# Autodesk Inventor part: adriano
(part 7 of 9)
sketch "スケッチ204"
  geometry: L1 (10, 18.464)-(6, 18.464) reference; L2 (10, 24.464)-(10, 18.464) reference; L3 (6.75, 24.064)-(7.75, 24.064); L4 (7.75, 24.064)-(7.75, 22.864); L5 (7.75, 22.864)-(6.75, 22.864); L6 (6.75, 22.864)-(6.75, 24.064); L7 (8.25, 24.064)-(9.25, 24.064); L8 (9.25, 24.064)-(9.25, 22.864); L9 (9.25, 22.864)-(8.25, 22.864); L10 (8.25, 22.864)-(8.25, 24.064); L11 (6.75, 22.364)-(7.75, 22.364); L12 (7.75, 22.364)-(7.75, 21.164); L13 (7.75, 21.164)-(6.75, 21.164); L14 (6.75, 21.164)-(6.75, 22.364); L15 (8.25, 22.364)-(9.25, 22.364); L16 (9.25, 22.364)-(9.25, 21.164); L17 (9.25, 21.164)-(8.25, 21.164); L18 (8.25, 21.164)-(8.25, 22.364); L19 (6.75, 20.664)-(7.75, 20.664); L20 (7.75, 20.664)-(7.75, 19.464); L21 (7.75, 19.464)-(6.75, 19.464); L22 (6.75, 19.464)-(6.75, 20.664); L23 (8.25, 20.664)-(9.25, 20.664); L24 (9.25, 20.664)-(9.25, 19.464); L25 (9.25, 19.464)-(8.25, 19.464); L26 (8.25, 19.464)-(8.25, 20.664); L27 (22.25, 22.364)-(23.25, 22.364); L28 (23.25, 22.364)-(23.25, 21.164); L29 (23.25, 21.164)-(22.25, 21.164); L30 (22.25, 21.164)-(22.25, 22.364); L31 (21.75, 22.364)-(21.75, 21.164); L32 (21.75, 21.164)-(20.75, 21.164); L33 (20.75, 21.164)-(20.75, 22.364); L34 (23.25, 22.864)-(22.25, 22.864); L35 (22.25, 22.864)-(22.25, 24.064); L36 (23.25, 24.064)-(23.25, 22.864); L37 (22.25, 24.064)-(23.25, 24.064); L38 (20.75, 20.664)-(21.75, 20.664); L39 (22.25, 20.664)-(23.25, 20.664); L40 (21.75, 20.664)-(21.75, 19.464); L41 (20.75, 19.464)-(20.75, 20.664); L42 (22.25, 19.464)-(22.25, 20.664); L43 (23.25, 20.664)-(23.25, 19.464); L44 (23.25, 19.464)-(22.25, 19.464); L45 (21.75, 19.464)-(20.75, 19.464); L46 (20.75, 22.364)-(21.75, 22.364); L47 (21.75, 22.864)-(20.75, 22.864); L48 (21.75, 24.064)-(21.75, 22.864); L49 (20.75, 22.864)-(20.75, 24.064); L50 (20.75, 24.064)-(21.75, 24.064); L51 (-5.75, 19.464)-(-5.75, 20.664); L52 (-4.75, 20.664)-(-4.75, 19.464); L53 (-4.75, 19.464)-(-5.75, 19.464); L54 (-7.25, 19.464)-(-7.25, 20.664); L55 (-6.25, 19.464)-(-7.25, 19.464); L56 (-6.25, 20.664)-(-6.25, 19.464); L57 (-7.25, 24.105)-(-6.25, 24.105); L58 (-6.25, 24.105)-(-6.25, 22.864); L59 (-6.25, 22.864)-(-7.25, 22.864); L60 (-7.25, 22.864)-(-7.25, 24.105); L61 (-5.75, 24.064)-(-4.75, 24.064); L62 (-4.75, 24.064)-(-4.75, 22.864); L63 (-7.25, 22.364)-(-6.25, 22.364); L64 (-5.75, 22.864)-(-5.75, 24.064)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; A1 r 1 centre (7.75, 24.564) between (7.75, 25.564) and (6.75, 24.564); A2 r 1 centre (8.25, 24.564) between (9.25, 24.564) and (8.25, 25.564); 7 further points
  constraints: 152 end point, 37 parallel, 21 perpendicular, 18 horizontal, 4 point on circle, 2 centre point
  dimensions: "d3442" = 1 distance of L3.start L3.end; "d3444" = 1 distance of L7.start L7.end; "d3445" = 0.5 distance between parallel lines of L10 L4; "d3446" = 0 distance between parallel lines of L18 L10; "d3447" = 0 distance between parallel lines of L18 L26; "d3448" = 0 distance between parallel lines of L16 L8; "d3449" = 0 distance between parallel lines of L24 L16; "d3450" = 1.2 distance of L7.end L8.end; "d3451" = 0.5 distance between parallel lines of L15 L9; "d3452" = 1.2 distance of L15.end L16.end; "d3453" = 0.5 distance between parallel lines of L23 L17; "d3454" = 1.2 distance of L23.end L24.end; "d3455" = 0 distance between parallel lines of L9 L5; "d3456" = 0 distance between parallel lines of L15 L11; "d3458" = 0 distance between parallel lines of L17 L13; "d3459" = 0 distance between parallel lines of L23 L19; "d3460" = 0 distance between parallel lines of L25 L21; "d3461" = 1 distance between parallel lines of L1 L25; "d3462" = 0.75 distance between parallel lines of L2 L24; "d3463" = 0 distance between parallel lines of L20 L12; "d3464" = 0 distance between parallel lines of L12 L4; "d3465" = 0 distance between parallel lines of L22 L14; "d3466" = 0 distance between parallel lines of L14 L6; "d3467" = 1 distance of L49.end L48.start; "d3468" = 1 distance of L35.end L36.start; "d3469" = 0.5 distance between parallel lines of L35 L48; "d3470" = 0 distance between parallel lines of L30 L35; "d3471" = 0 distance between parallel lines of L30 L42; "d3472" = 0 distance between parallel lines of L28 L36; "d3473" = 0 distance between parallel lines of L43 L28; "d3474" = 1.2 distance of L36.start L34.start; "d3475" = 0.5 distance between parallel lines of L27 L34; "d3476" = 1.2 distance of L27.end L28.end; "d3477" = 0.5 distance between parallel lines of L39 L29; "d3478" = 1.2 distance of L39.end L43.end; "d3479" = 0 distance between parallel lines of L34 L47; "d3480" = 0 distance between parallel lines of L27 L46; "d3481" = 0 distance between parallel lines of L29 L32; "d3482" = 0 distance between parallel lines of L39 L38; "d3483" = 0 distance between parallel lines of L44 L45; "d3484" = 0 distance between parallel lines of L40 L31; "d3485" = 0 distance between parallel lines of L31 L48; "d3486" = 0 distance between parallel lines of L41 L33; "d3487" = 0 distance between parallel lines of L33 L49; "d3488" = 1 distance of L57.start L57.end; "d3489" = 1 distance of L61.start L61.end; "d3490" = 0.5 distance between parallel lines of L64 L58; "d3491" = 0 distance between parallel lines of L71 L64; "d3492" = 0 distance between parallel lines of L71 L51; "d3493" = 0 distance between parallel lines of L69 L62; "d3494" = 0 distance between parallel lines of L52 L69; "d3495" = 1.2 distance of L61.end L62.end; "d3496" = 0.5 distance between parallel lines of L68 L70; "d3497" = 1.2 distance of L68.end L67.start; "d3498" = 0.5 distance between parallel lines of L65 L67; "d3499" = 1.2 distance of L52.start L52.end; "d3500" = 0 distance between parallel lines of L70 L59; "d3501" = 0 distance between parallel lines of L68 L63; "d3502" = 0 distance between parallel lines of L67 L66; "d3503" = 0 distance between parallel lines of L65 L74; "d3504" = 0 distance between parallel lines of L53 L55; "d3505" = 0 distance between parallel lines of L56 L73; "d3506" = 0 distance between parallel lines of L73 L58; "d3507" = 0 distance between parallel lines of L54 L72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
extrude "押し出し193" cut sketch "スケッチ204" distance "d3515" = 16; taper "d3516" = 0 deg
sketch "スケッチ205"
  geometry: L1 (12.25, 5.3)-(12.25, 6.5) reference; L2 (12.25, 6.5)-(13.25, 6.5) reference; L3 (13.25, 6.5)-(13.25, 5.3) reference; L4 (13.25, 5.3)-(12.25, 5.3) reference; L5 (12.25, 7)-(12.25, 8.2) reference; L6 (12.25, 8.2)-(13.25, 8.2) reference; L7 (13.25, 8.2)-(13.25, 7) reference; L8 (13.25, 7)-(12.25, 7) reference; L9 (10.75, 4.8)-(11.75, 4.8) reference; L10 (11.75, 4.8)-(11.75, 3.6) reference; L11 (11.75, 3.6)-(10.75, 3.6) reference; L12 (10.75, 3.6)-(10.75, 4.8) reference; L13 (13.25, 4.8)-(13.25, 3.6) reference; L14 (13.25, 3.6)-(12.25, 3.6) reference; L15 (12.25, 3.6)-(12.25, 4.8) reference; L16 (12.25, 4.8)-(13.25, 4.8) reference; L17 (10.75, 5.3)-(10.75, 6.5) reference; L18 (10.75, 6.5)-(11.75, 6.5) reference; L19 (11.75, 6.5)-(11.75, 5.3) reference; L20 (11.75, 5.3)-(10.75, 5.3) reference; L21 (10.75, 7)-(10.75, 8.241) reference; L22 (10.75, 8.241)-(11.75, 8.241) reference; L23 (11.75, 8.241)-(11.75, 7) reference; L24 (11.75, 7)-(10.75, 7) reference; L25 (9.5, 2.6)-(9.5, 8.6) reference; L26 (14.5, 2.6)-(9.5, 2.6) reference; L27 (10, 9.1)-(14, 9.1); L28 (14, 9.1)-(14, 3.1); L29 (14, 3.1)-(10, 3.1); L30 (10, 3.1)-(10, 9.1); L31 (38, 9.1)-(42, 9.1); L32 (42, 9.1)-(42, 3.1); L33 (42, 3.1)-(38, 3.1); L34 (38, 3.1)-(38, 9.1); L35 (37.5, 2.6)-(37.5, 8.6) reference; 1 further point
  constraints: 16 end point, 4 parallel, 2 horizontal, 2 perpendicular
  dimensions: "d3517" = 4 distance of L28.end L29.end; "d3519" = 4 distance of L32.end L33.end; "d3520" = 0.5 distance between parallel lines of L26 L29; "d3521" = 0 distance between parallel lines of L33 L29; "d3522" = 0.5 distance between parallel lines of L30 L25; "d3523" = 0.5 distance between parallel lines of L35 L34; "d3524" = 6 distance of L31.end L32.end; "d3525" = 0 distance between parallel lines of L31 L27
extrude "押し出し194" cut sketch "スケッチ205" distance "d3526" = 0.5; taper "d3527" = 0 deg
sketch "スケッチ206"
  geometry: L1 (0, 0)-(26, 0) reference; L2 (0, -1.6)-(0, 0) reference; L3 (10.33, 7)-(10.33, 1); L4 (10.33, 1)-(15.33, 1); L5 (15.33, 1)-(15.33, 7); A1 r 2.5 centre (12.83, 7) between (15.33, 7) and (10.33, 7); 1 further point
  constraints: 6 end point, 2 parallel, 2 point on circle, 1 centre point, 1 perpendicular
  dimensions: "d3528" = 1 distance between parallel lines of L1 L4; "d3529" = 5 distance of L3.end L4.end; "d3530" = 6 distance of L4.end L5.end; "d3531" = 0 vertical distance of L5.end A1.centre; "d3532" = 0 vertical distance of A1.centre L3.start
extrude "押し出し195" join sketch "スケッチ206" distance "d3533" = 8; taper "d3534" = 0 deg
sketch "スケッチ207"
  geometry: L1 (10.33, 7)-(10.33, 1) reference; L2 (10.33, 1)-(15.33, 1) reference; L3 (15.33, 1)-(15.33, 7) reference; L4 (10.33, 7)-(10.33, 1); L5 (10.33, 1)-(15.33, 1); L6 (15.33, 1)-(15.33, 7); A1 r 2.5 centre (12.83, 7) between (15.33, 7) and (10.33, 7) reference; A2 r 2.5 centre (12.83, 7) between (15.33, 7) and (10.33, 7); 1 further point
  constraints: 6 end point, 4 tangent, 3 equal length, 2 point on circle, 1 centre point, 1 coincident
extrude "押し出し196" cut sketch "スケッチ207" distance "d3535" = 0.5; taper "d3536" = 0 deg
sketch "スケッチ208"
  geometry: L1 (10.33, 1)-(10.33, 7) reference; L2 (9.83, 7)-(10.33, 7); L3 (15.33, 7)-(15.83, 7); A1 r 2.5 centre (12.83, 7) between (15.33, 7) and (10.33, 7) reference; A2 r 3 centre (12.83, 7) between (15.83, 7) and (9.83, 7); A3 r 2.5 centre (12.83, 7) between (15.33, 7) and (10.33, 7); 1 further point
  constraints: 4 end point, 4 point on circle, 2 centre point, 2 coincident, 1 collinear, 1 perpendicular
  dimensions: "d3537" = 0.5 distance of L2.start L1.end
extrude "押し出し197" join sketch "スケッチ208" distance "d3538" = 8; taper "d3539" = 0 deg
sketch "スケッチ209"
  geometry: L1 (10.33, 1)-(10.33, 7) reference; L2 (9.83, 7)-(10.33, 7) reference; L3 (10.33, 7)-(10.33, 1); L4 (10.33, 1)-(15.33, 1); L5 (15.33, 1)-(15.33, 7); A1 r 3 centre (12.83, 7) between (15.83, 7) and (9.83, 7) reference; A2 r 2.5 centre (12.83, 7) between (15.33, 7) and (10.33, 7); 1 further point
  constraints: 6 end point, 3 perpendicular, 2 point on circle, 2 tangent, 1 centre point, 1 coincident
extrude "押し出し198" cut sketch "スケッチ209" distance "d3540" = 0.5; taper "d3541" = 0 deg
sketch "スケッチ210"
  geometry: L1 (10.33, 1)-(10.33, 7) reference; L2 (15.33, 1)-(10.33, 1) reference; L3 (11.58, 6.6)-(12.58, 6.6); L4 (12.58, 6.6)-(12.58, 5.4); L5 (12.58, 5.4)-(11.58, 5.4); L6 (11.58, 5.4)-(11.58, 6.6); L7 (13.08, 6.6)-(14.08, 6.6); L8 (14.08, 6.6)-(14.08, 5.4); L9 (14.08, 5.4)-(13.08, 5.4); L10 (13.08, 5.4)-(13.08, 6.6); L11 (11.58, 4.9)-(12.58, 4.9); L12 (12.58, 4.9)-(12.58, 3.7); L13 (12.58, 3.7)-(11.58, 3.7); L14 (11.58, 3.7)-(11.58, 4.9); L15 (13.08, 4.9)-(14.08, 4.9); L16 (14.08, 4.9)-(14.08, 3.7); L17 (14.08, 3.7)-(13.08, 3.7); L18 (13.08, 3.7)-(13.08, 4.9); L19 (11.58, 3.2)-(12.58, 3.2); L20 (12.58, 3.2)-(12.58, 2); L21 (12.58, 2)-(11.58, 2); L22 (11.58, 2)-(11.58, 3.2); L23 (13.08, 3.2)-(14.08, 3.2); L24 (14.08, 3.2)-(14.08, 2); L25 (14.08, 2)-(13.08, 2); L26 (13.08, 2)-(13.08, 3.2); 1 further point
  constraints: 48 end point, 12 parallel, 6 horizontal, 6 perpendicular
  dimensions: "d3542" = 1 distance of L3.start L3.end; "d3544" = 1 distance of L7.start L7.end; "d3545" = 0.5 distance between parallel lines of L4 L10; "d3546" = 1.2 distance of L7.end L8.end; "d3547" = 0.5 distance between parallel lines of L9 L15; "d3548" = 0.5 distance between parallel lines of L23 L17; "d3549" = 1.2 distance of L15.end L16.end; "d3550" = 1.2 distance of L23.end L24.end; "d3551" = 0 distance between parallel lines of L16 L8; "d3552" = 0 distance between parallel lines of L18 L10; "d3553" = 0 distance between parallel lines of L26 L18; "d3554" = 0 distance between parallel lines of L25 L21; "d3555" = 0 distance between parallel lines of L9 L5; "d3556" = 0 distance between parallel lines of L15 L11; "d3557" = 0 distance between parallel lines of L17 L13; "d3558" = 0 distance between parallel lines of L23 L19; "d3559" = 1 distance between parallel lines of L2 L21; "d3560" = 1.25 distance between parallel lines of L22 L1; "d3561" = 0 distance between parallel lines of L22 L14; "d3562" = 0 distance between parallel lines of L14 L6; "d3563" = 0 distance between parallel lines of L12 L4; "d3564" = 0 distance between parallel lines of L20 L12
extrude "押し出し199" cut sketch "スケッチ210" distance "d3565" = 16; taper "d3566" = 0 deg
sketch "スケッチ211"
  geometry: L1 (11.58, 2)-(11.58, 3.2) reference; L2 (11.58, 3.2)-(12.58, 3.2) reference; L3 (12.58, 3.2)-(12.58, 2) reference; L4 (12.58, 2)-(11.58, 2) reference; L5 (11.58, 3.7)-(11.58, 4.9) reference; L6 (11.58, 4.9)-(12.58, 4.9) reference; L7 (12.58, 4.9)-(12.58, 3.7) reference; L8 (12.58, 3.7)-(11.58, 3.7) reference; L9 (11.58, 5.4)-(11.58, 6.6) reference; L10 (11.58, 6.6)-(12.58, 6.6) reference; L11 (12.58, 6.6)-(12.58, 5.4) reference; L12 (12.58, 5.4)-(11.58, 5.4) reference; L13 (13.08, 5.4)-(13.08, 6.6) reference; L14 (13.08, 6.6)-(14.08, 6.6) reference; L15 (14.08, 6.6)-(14.08, 5.4) reference; L16 (14.08, 5.4)-(13.08, 5.4) reference; L17 (13.08, 3.7)-(13.08, 4.9) reference; L18 (13.08, 4.9)-(14.08, 4.9) reference; L19 (14.08, 4.9)-(14.08, 3.7) reference; L20 (14.08, 3.7)-(13.08, 3.7) reference; L21 (13.08, 2)-(13.08, 3.2) reference; L22 (13.08, 3.2)-(14.08, 3.2) reference; L23 (14.08, 3.2)-(14.08, 2) reference; L24 (14.08, 2)-(13.08, 2) reference; L25 (10.33, 1)-(10.33, 7) reference; L26 (15.33, 1)-(10.33, 1) reference; L27 (10.83, 7.5)-(14.83, 7.5); L28 (14.83, 7.5)-(14.83, 1.5); L29 (14.83, 1.5)-(10.83, 1.5); L30 (10.83, 1.5)-(10.83, 7.5); 1 further point
  constraints: 8 end point, 2 parallel, 1 horizontal, 1 perpendicular
  dimensions: "d3567" = 0.5 distance between parallel lines of L25 L30; "d3568" = 0.5 distance between parallel lines of L26 L29; "d3569" = 4 distance of L28.end L29.end; "d3570" = 6 distance of L27.end L28.end
extrude "押し出し200" cut sketch "スケッチ211" distance "d3571" = 0.5; taper "d3572" = 0 deg
sketch "スケッチ213"
  geometry: L1 (-20.5, -15.619)-(-16.5, -15.619); L2 (-16.5, -15.619)-(-16.5, -32.129); L3 (-16.5, -32.129)-(-20.5, -32.129); L4 (-20.5, -32.129)-(-20.5, -15.619); L5 (-8.5, -15.619)-(-4.5, -15.619); L6 (-4.5, -15.619)-(-4.5, -32.129); L7 (-4.5, -32.129)-(-8.5, -32.129); L8 (-8.5, -32.129)-(-8.5, -15.619); L9 (-20, -26)-(-30, -26); L10 (-30, -26)-(-30, -22); L11 (-30, -22)-(-20, -22); L12 (-20, -22)-(-20, -26); L13 (9, -2.965)-(13, -2.965); L14 (13, -2.965)-(13, -44.448); L15 (13, -44.448)-(9, -44.448); L16 (9, -44.448)-(9, -2.965); L17 (13, -8)-(19, -8); L18 (19, -8)-(19, -12); L19 (19, -12)-(13, -12); L20 (13, -12)-(13, -8); L21 (13, -22)-(19, -22); L22 (19, -22)-(19, -26); L23 (19, -26)-(13, -26); L24 (13, -26)-(13, -22); L25 (13, -36)-(19, -36); L26 (19, -36)-(19, -40); L27 (19, -40)-(13, -40); L28 (13, -40)-(13, -36); L29 (0, -13)-(-31, -13) reference; L30 (-31, -13)-(-31, -35) reference; L31 (2, -2)-(19, -2) reference; L32 (19, -2)-(19, -46) reference; L33 (-29, -33)-(-29, -15) reference; L34 (21, -48)-(21, 0) reference; L35 (19, -8)-(21, -8); L36 (21, -8)-(21, -12); L37 (21, -12)-(19, -12); L38 (19, -12)-(19, -8); L39 (19, -22)-(21, -22); L40 (21, -22)-(21, -26); L41 (21, -26)-(19, -26); L42 (19, -26)-(19, -22); L43 (19, -36)-(21, -36); L44 (21, -36)-(21, -40); L45 (21, -40)-(19, -40); L46 (19, -40)-(19, -36); 1 further point
  constraints: 80 end point, 20 parallel, 10 horizontal, 10 perpendicular, 3 point on line
  dimensions: "d3585" = 1 distance between parallel lines of L30 L10; "d3586" = 10 distance of L10.end L11.end; "d3587" = 4 distance of L11.end L9.start; "d3588" = 9 distance between parallel lines of L11 L29; "d3589" = 4 distance of L1.start L1.end; "d3590" = 4 distance of L5.start L5.end; "d3591" = 4 distance of L13.start L13.end; "d3592" = 4 distance of L17.end L18.end; "d3593" = 4 distance of L21.end L22.end; "d3594" = 4 distance of L25.end L26.end; "d3595" = 20 distance between parallel lines of L31 L21; "d3596" = 10 distance between parallel lines of L21 L19; "d3597" = 10 distance between parallel lines of L25 L23; "d3598" = 0 distance between parallel lines of L32 L22; "d3599" = 0 distance between parallel lines of L32 L18; "d3600" = 0 distance between parallel lines of L18 L26; "d3601" = 6 distance of L17.start L17.end; "d3602" = 0 distance between parallel lines of L24 L20; "d3603" = 0 distance between parallel lines of L28 L24; "d3604" = 8.5 distance between parallel lines of L33 L4; "d3605" = 8 distance between parallel lines of L8 L2; "d3606" = 6 distance between parallel lines of L32 L14
extrude "押し出し202" cut sketch "スケッチ213" distance "d3583" = 8; taper "d3584" = 0 deg
sketch "スケッチ214"
  geometry: L1 (21, -48)-(21, 0) reference; L2 (19, -22)-(21, -22); L3 (21, -22)-(21, -26); L4 (21, -26)-(19, -26); L5 (19, -26)-(19, -22); L6 (19, -8)-(20.5, -8); L7 (20.5, -8)-(20.5, -12); L8 (20.5, -12)-(19, -12); L9 (19, -12)-(19, -8); L10 (19, -36)-(20.5, -36); L11 (20.5, -36)-(20.5, -40); L12 (20.5, -40)-(19, -40); L13 (19, -40)-(19, -36); 1 further point
  constraints: 24 end point, 6 parallel, 3 horizontal, 3 perpendicular, 1 point on line
  dimensions: "d3609" = 1.5 distance of L11.end L12.end; "d3611" = 1.5 distance of L7.end L8.end
extrude "押し出し203" cut sketch "スケッチ214" distance "d3607" = 8; taper "d3608" = 0 deg
sketch "スケッチ216"
  geometry: L1 (13, -16.536)-(3, -16.536) reference; L2 (4.65, -7.236)-(5.65, -7.236); L3 (5.65, -7.236)-(5.65, -11.236); L4 (5.65, -11.236)-(4.65, -11.236); L5 (4.65, -11.236)-(4.65, -7.236); L6 (6.15, -7.236)-(7.75, -7.236); L7 (7.75, -7.236)-(7.75, -11.236); L8 (7.75, -11.236)-(6.15, -11.236); L9 (6.15, -11.236)-(6.15, -7.236); L10 (4.65, -12.036)-(5.25, -12.036); L11 (5.25, -12.036)-(5.25, -16.036); L12 (5.25, -16.036)-(4.65, -16.036); L13 (4.65, -16.036)-(4.65, -12.036); L14 (6.15, -12.036)-(7.75, -12.036); L15 (7.75, -12.036)-(7.75, -16.036); L16 (7.75, -16.036)-(6.15, -16.036); L17 (6.15, -16.036)-(6.15, -12.036); L18 (8.25, -7.236)-(9.85, -7.236); L19 (9.85, -7.236)-(9.85, -11.236); L20 (9.85, -11.236)-(8.25, -11.236); L21 (8.25, -11.236)-(8.25, -7.236); L22 (8.25, -12.036)-(9.85, -12.036); L23 (9.85, -12.036)-(9.85, -16.036); L24 (9.85, -16.036)-(8.25, -16.036); L25 (8.25, -16.036)-(8.25, -12.036); L26 (10.35, -7.236)-(11.35, -7.236); L27 (11.35, -7.236)-(11.35, -11.236); L28 (11.35, -11.236)-(10.35, -11.236); L29 (10.35, -11.236)-(10.35, -7.236); L30 (10.35, -12.036)-(11.35, -12.036); L31 (11.35, -12.036)-(11.35, -16.036); L32 (11.35, -16.036)-(10.35, -16.036); L33 (10.35, -16.036)-(10.35, -12.036); L34 (4.65, -6.736)-(5.65, -6.736); L35 (6.15, -6.736)-(9.85, -6.736); L36 (10.35, -6.736)-(11.35, -6.736); L37 (7.708, -3.399)-(7.795, -4.395); L38 (8.292, -3.399)-(8.205, -4.395); A1 r 5 centre (8, -7.536) between (13, -7.536) and (3, -7.536) reference; A2 r 1.85 centre (8, -6.736) between (9.85, -6.736) and (6.15, -6.736); A3 r 2.35 centre (8, -6.736) between (7.795, -4.395) and (5.65, -6.736); A4 r 3.35 centre (8, -6.736) between (7.708, -3.399) and (4.65, -6.736); A5 r 2.35 centre (8, -6.736) between (10.35, -6.736) and (8.205, -4.395); A6 r 3.35 centre (8, -6.736) between (11.35, -6.736) and (8.292, -3.399); 1 further point
  constraints: 74 end point, 16 parallel, 10 point on circle, 9 perpendicular, 8 horizontal, 5 centre point, 3 coincident, 2 collinear
  dimensions: "d3667" = 1 distance of L2.start L2.end; "d3669" = 1 distance of L26.start L26.end; "d3670" = 0.5 distance between parallel lines of L9 L3; "d3671" = 0.5 distance between parallel lines of L29 L19; "d3672" = 0.5 distance between parallel lines of L21 L7; "d3673" = 1.6 distance of L6.start L6.end; "d3674" = 1.6 distance of L18.start L18.end; "d3675" = 0.25 distance from line of L7 A1.centre; "d3676" = 0 distance between parallel lines of L13 L5; "d3677" = 0 distance between parallel lines of L15 L7; "d3678" = 0 distance between parallel lines of L17 L9; "d3679" = 0 distance between parallel lines of L25 L21; "d3680" = 0 distance between parallel lines of L19 L23; "d3681" = 0 distance between parallel lines of L33 L29; "d3682" = 0 distance between parallel lines of L31 L27; "d3683" = 0.5 distance between parallel lines of L12 L1; "d3684" = 0 distance between parallel lines of L16 L12; "d3685" = 0 distance between parallel lines of L24 L16; "d3686" = 0 distance between parallel lines of L32 L24; "d3687" = 4 distance of L30.end L31.end; "d3688" = 0.8 distance between parallel lines of L30 L28; "d3689" = 0 distance between parallel lines of L28 L20; "d3690" = 0 distance between parallel lines of L8 L20; "d3691" = 0 distance between parallel lines of L4 L8; "d3692" = 4 distance of L26.end L27.end; "d3693" = 0 distance between parallel lines of L26 L18; "d3694" = 0 distance between parallel lines of L6 L18; "d3695" = 0 distance between parallel lines of L14 L22; "d3696" = 0 distance between parallel lines of L22 L30; "d3697" = 0 distance between parallel lines of L14 L10; "d3698" = 0.5 distance of L2.start L34.start; "d3699" = 0 distance between parallel lines of L6 L2; "d3700" = 0 distance between parallel lines of L34 L35; "d3701" = 0 distance between parallel lines of L36 L35; "d3702" = 0.5 distance of L35.start L34.end; "d3703" = 0.5 distance of L36.start L35.end; "d3704" = 0 distance of A2.centre A3.centre; "d3705" = 0 distance of A2.centre A3.centre; "d3706" = 0 horizontal distance of L2.end L34.end; "d3707" = 0 horizontal distance of L26.start L36.start; "d3708" = 0 horizontal distance of L26.end L36.end; "d3709" = 0 vertical distance of L38.end L37.end; "d3711" = 85 deg dimension on A2.centre L37.start L34.start; "d3712" = 85 deg dimension on A2.centre L34.end L37.end; "d3714" = 85 deg dimension on A2.centre L36.end L38.start; "d3717" = 0 distance from line of L35 A2.centre; "d3718" = 0 horizontal distance of L2.start L34.start
extrude "押し出し205" cut sketch "スケッチ216" distance "d3715" = 10; taper "d3716" = 0 deg
sketch "スケッチ217"
  geometry: L1 (5, 2)-(5, 11) reference; L2 (11, 2)-(5, 2) reference; L3 (11, 11)-(11, 2) reference; L4 (5.5, 10.5)-(7.75, 10.5); L5 (7.75, 10.5)-(7.75, 7.5); L6 (7.75, 7.5)-(5.5, 7.5); L7 (5.5, 7.5)-(5.5, 10.5); L8 (8.25, 10.5)-(10.5, 10.5); L9 (10.5, 10.5)-(10.5, 7.5); L10 (10.5, 7.5)-(8.25, 7.5); L11 (8.25, 7.5)-(8.25, 10.5); L12 (5.5, 7)-(7.75, 7); L13 (7.75, 7)-(7.75, 2.5); L14 (7.75, 2.5)-(5.5, 2.5); L15 (5.5, 2.5)-(5.5, 7); L16 (8.25, 7)-(10.5, 7); L17 (10.5, 7)-(10.5, 2.5); L18 (10.5, 2.5)-(8.25, 2.5); L19 (8.25, 2.5)-(8.25, 7); L20 (5.5, 11)-(6.5, 11); L21 (7, 11)-(9, 11); L22 (9.5, 11)-(10.5, 11); L23 (7.782, 13.49)-(7.869, 12.494); L24 (8.218, 13.49)-(8.131, 12.494); A1 r 3 centre (8, 11) between (11, 11) and (5, 11) reference; A2 r 1 centre (8, 11) between (9, 11) and (7, 11); A3 r 1.5 centre (8, 11) between (7.869, 12.494) and (6.5, 11); A4 r 2.5 centre (8, 11) between (7.782, 13.49) and (5.5, 11); A5 r 1.5 centre (8, 11) between (9.5, 11) and (8.131, 12.494); A6 r 2.5 centre (8, 11) between (10.5, 11) and (8.218, 13.49); 1 further point
  constraints: 42 end point, 10 point on circle, 9 parallel, 5 centre point, 5 perpendicular, 4 coincident, 4 horizontal, 1 collinear
  dimensions: "d3719" = 0.5 distance between parallel lines of L1 L15; "d3720" = 0.5 distance between parallel lines of L19 L13; "d3721" = 0.5 distance between parallel lines of L3 L17; "d3722" = 0.25 distance from line of A1.centre L13; "d3723" = 0 distance between parallel lines of L15 L7; "d3724" = 0 distance between parallel lines of L13 L5; "d3725" = 0 distance between parallel lines of L19 L11; "d3726" = 0 distance between parallel lines of L17 L9; "d3727" = 0.5 distance between parallel lines of L2 L14; "d3728" = 0 distance between parallel lines of L14 L18; "d3729" = 0.5 distance between parallel lines of L16 L10; "d3730" = 4.5 distance of L16.end L17.end; "d3731" = 3 distance of L8.end L9.end; "d3732" = 0 distance between parallel lines of L16 L12; "d3733" = 0 distance between parallel lines of L10 L6; "d3734" = 0 distance between parallel lines of L8 L4; "d3735" = 0.5 distance between parallel lines of L8 L22; "d3736" = 0 distance between parallel lines of L22 L21; "d3737" = 0 distance between parallel lines of L20 L21; "d3738" = 0.5 distance of L21.start L20.end; "d3739" = 0.5 distance of L22.start L21.end; "d3740" = 1 distance of L20.start L20.end; "d3741" = 1 distance of L22.start L22.end; "d3742" = 0 horizontal distance of L8.end L22.end; "d3743" = 0 distance from line of L7 L20.start; "d3744" = 0 distance from line of L21 A2.centre; "d3745" = 85 deg dimension on A2.centre L23.start L20.start; "d3746" = 85 deg dimension on A6.centre L20.end L23.end; "d3747" = 85 deg dimension on A2.centre L22.start L24.end; "d3748" = 85 deg dimension on A2.centre L22.end L24.start
extrude "押し出し206" cut sketch "スケッチ217" distance "d3749" = 10; taper "d3750" = 0 deg
sketch "スケッチ218"
  geometry: L1 (0, 6)-(0, 0) reference; L2 (-0.5, 6)-(-0.5, 0) reference; L3 (0, 7)-(0, -1); A1 r 4 centre (0, 3) between (0, -1) and (0, 7); 1 further point
  constraints: 2 end point, 2 point on circle, 1 centre point, 1 midpoint, 1 parallel, 1 point on line
  dimensions: "d3751" = 1 distance of L3.start L1.start
extrude "押し出し207" join sketch "スケッチ218" distance "d3752" = 1; taper "d3753" = 0 deg
sketch "スケッチ219"
  geometry: L1 (0.5, 0)-(0.5, 1) reference; L2 (0.5, 0.5)-(0.5, 1); L3 (0.5, -6.5)-(0.5, -7); A1 r 4 centre (0.5, -3) between (0.5, -7) and (0.5, 1) reference; A2 r 4 centre (0.5, -3) between (0.5, -7) and (0.5, 1); A3 r 3.5 centre (0.5, -3) between (0.5, -6.5) and (0.5, 0.5); 1 further point
  constraints: 4 end point, 4 point on circle, 2 centre point, 2 coincident, 2 collinear, 1 midpoint
extrude "押し出し208" join sketch "スケッチ219" distance "d3754" = 4; taper "d3755" = 0 deg
sketch "スケッチ222"
  geometry: L1 (-4.5, 6)-(-4, 6) reference; L2 (-8.5, 5)-(-7.5, 5); L3 (-7.5, 5)-(-7.5, 2.5); L4 (-7.5, 2.5)-(-8.5, 2.5); L5 (-8.5, 2.5)-(-8.5, 5); L6 (-9, 5)-(-10, 5); L7 (-10, 5)-(-10, 2.5); L8 (-10, 2.5)-(-9, 2.5); L9 (-9, 2.5)-(-9, 5); L10 (-7, 5)-(-6, 5); L11 (-6, 5)-(-6, 2.5); L12 (-6, 2.5)-(-7, 2.5); L13 (-7, 2.5)-(-7, 5); L14 (-10.5, 5)-(-11.3, 5); L15 (-11.3, 5)-(-11.3, 2.5); L16 (-11.3, 2.5)-(-10.5, 2.5); L17 (-10.5, 2.5)-(-10.5, 5); L18 (-5.5, 5)-(-4.7, 5); L19 (-4.7, 5)-(-4.7, 2.5); L20 (-4.7, 2.5)-(-5.5, 2.5); L21 (-5.5, 2.5)-(-5.5, 5); L22 (-8.25, 7)-(-8.25, 2.5) reference; 1 further point
  constraints: 40 end point, 10 parallel, 5 horizontal, 5 perpendicular
  dimensions: "d3785" = 1 distance of L2.start L2.end; "d3787" = 0.25 distance between parallel lines of L22 L5; "d3788" = 0.5 distance between parallel lines of L13 L3; "d3789" = 0.5 distance between parallel lines of L21 L11; "d3790" = 0.5 distance between parallel lines of L9 L5; "d3791" = 0.5 distance between parallel lines of L17 L7; "d3792" = 1 distance of L10.start L10.end; "d3793" = 1 distance of L6.start L6.end; "d3794" = 0.8 distance of L14.start L14.end; "d3795" = 0.8 distance of L18.start L18.end; "d3796" = 2.5 distance of L18.end L19.end; "d3797" = 1 distance between parallel lines of L1 L18; "d3798" = 0 distance between parallel lines of L10 L18; "d3799" = 0 distance between parallel lines of L2 L10; "d3800" = 0 distance between parallel lines of L6 L2; "d3801" = 0 distance between parallel lines of L12 L20; "d3802" = 0 distance between parallel lines of L4 L12; "d3803" = 0 distance between parallel lines of L4 L8; "d3804" = 0 distance between parallel lines of L16 L8
extrude "押し出し211" cut sketch "スケッチ222" distance "d3805" = 14; taper "d3806" = 0 deg
sketch "スケッチ223"
  geometry: L1 (0, 0)-(0, 15.864) reference; L2 (0, 5)-(-1.2, 5); L3 (-1.2, 5)-(-1.2, 2.5); L4 (-1.2, 2.5)-(0, 2.5); L5 (0, 2.5)-(0, 5); L6 (0, 6)-(-4, 6) reference; 1 further point
  constraints: 8 end point, 2 parallel, 1 horizontal, 1 perpendicular, 1 point on line
  dimensions: "d3807" = 1 distance between parallel lines of L2 L6; "d3808" = 2.5 distance of L2.end L3.end; "d3809" = 1.2 distance of L2.start L2.end
extrude "押し出し212" cut sketch "スケッチ223" distance "d3810" = 14; taper "d3811" = 0 deg
sketch "スケッチ224"
  geometry: L1 (0, -7)-(0, 1) reference; L2 (0, 0.2)-(0, -6.2); A1 r 4 centre (0, -3) between (0, -7) and (0, 1) reference; A2 r 3.2 centre (0, -3) between (0, -6.2) and (0, 0.2); 1 further point
  constraints: 2 end point, 2 point on circle, 1 centre point, 1 coincident, 1 collinear, 1 point on line
  dimensions: "d3813" = 0.8 distance of L1.start L2.end
extrude "押し出し213" cut sketch "スケッチ224" distance "d3814" = 0.5; taper "d3815" = 0 deg
sketch "スケッチ225"
  geometry: L1 (0, 4)-(0, 0) reference; L2 (0, 5)-(0, -1); A1 r 3 centre (0, 2) between (0, -1) and (0, 5); 1 further point
  constraints: 2 end point, 2 point on circle, 1 centre point, 1 collinear, 1 midpoint, 1 point on line
  dimensions: "d3816" = 1 distance of L2.start L1.start
extrude "押し出し214" join sketch "スケッチ225" distance "d3817" = 1; taper "d3818" = 0 deg
sketch "スケッチ226"
  geometry: L1 (0.5, -5)-(0.5, -4) reference; L2 (0.5, 0)-(0.5, 1) reference; L3 (0.5, 1)-(0.5, 0.5); L4 (0.5, -4.5)-(0.5, -5); A1 r 3 centre (0.5, -2) between (0.5, -5) and (0.5, 1) reference; A2 r 2.5 centre (0.5, -2) between (0.5, -4.5) and (0.5, 0.5); A3 r 3 centre (0.5, -2) between (0.5, -5) and (0.5, 1); 1 further point
  constraints: 4 end point, 4 point on circle, 2 centre point, 2 coincident, 2 collinear, 1 midpoint
extrude "押し出し215" join sketch "スケッチ226" distance "d3819" = 3; taper "d3820" = 0 deg
sketch "スケッチ227"
  geometry: L1 (0, -5)-(0, 1) reference; L2 (0, 0.2)-(0, -4.2); A1 r 3 centre (0, -2) between (0, -5) and (0, 1) reference; A2 r 2.2 centre (0, -2) between (0, -4.2) and (0, 0.2); 1 further point
  constraints: 2 end point, 2 point on circle, 1 centre point, 1 coincident, 1 collinear, 1 point on line
  dimensions: "d3821" = 0.8 distance of L1.end L2.start
extrude "押し出し216" cut sketch "スケッチ227" distance "d3822" = 0.5; taper "d3823" = 0 deg
sketch "スケッチ228"
  geometry: L1 (-10.5, 18.464)-(-10, 18.464) reference; L2 (-10, 20.464)-(-9, 20.464); L3 (-9, 20.464)-(-9, 18.464); L4 (-9, 18.464)-(-10, 18.464); L5 (-10, 18.464)-(-10, 20.464); L6 (-8.5, 20.464)-(-7.5, 20.464); L7 (-7.5, 20.464)-(-7.5, 18.464); L8 (-7.5, 18.464)-(-8.5, 18.464); L9 (-8.5, 18.464)-(-8.5, 20.464); L10 (-7, 20.464)-(-6, 20.464); L11 (-6, 20.464)-(-6, 18.464); L12 (-6, 18.464)-(-7, 18.464); L13 (-7, 18.464)-(-7, 20.464); L14 (-8.25, 22.364)-(-8.25, 21.164) reference; 1 further point
  constraints: 24 end point, 6 parallel, 3 horizontal, 3 perpendicular
  dimensions: "d3824" = 0.25 distance between parallel lines of L9 L14; "d3825" = 1 distance of L6.start L6.end; "d3826" = 0.5 distance between parallel lines of L3 L9; "d3827" = 0.5 distance between parallel lines of L13 L7; "d3828" = 1 distance of L2.start L2.end; "d3829" = 1 distance of L10.start L10.end; "d3830" = 2 distance of L10.end L11.end; "d3831" = 0 distance between parallel lines of L8 L12; "d3832" = 0 distance between parallel lines of L4 L8; "d3833" = 0 distance between parallel lines of L1 L4; "d3834" = 0 distance between parallel lines of L10 L6; "d3835" = 0 distance between parallel lines of L2 L6
extrude "押し出し217" cut sketch "スケッチ228" distance "d3836" = 8; taper "d3837" = 0 deg
sketch "スケッチ229"
  geometry: L1 (-1.5, 3)-(-0.5, 3); L2 (-0.5, 3)-(-0.5, 1); L3 (-0.5, 1)-(-1.5, 1); L4 (-1.5, 1)-(-1.5, 3); L5 (-0.5, 1.1)-(-0.5, 9.5) reference; L6 (-2.236, 3)-(-2.828, 3) reference; L7 (-2.828, 1)-(-2.236, 1) reference; 1 further point
  constraints: 8 end point, 2 parallel, 1 horizontal, 1 perpendicular
  dimensions: "d3838" = 1 distance of L1.start L1.end; "d3840" = 0 distance between parallel lines of L5 L2; "d3841" = 0 distance between parallel lines of L1 L6; "d3842" = 0 distance between parallel lines of L7 L3
extrude "押し出し218" cut sketch "スケッチ229" distance "d3843" = 40; taper "d3844" = 0 deg
sketch "スケッチ230"
  geometry: L1 (-10.2, 17.464)-(-11, 17.464) reference; L2 (-10.5, 24.464)-(-10, 24.464); L3 (-6, 24.464)-(-5.5, 24.464); A1 r 2 centre (-8, 24.464) between (-6, 24.464) and (-10, 24.464) reference; A2 r 2.5 centre (-8, 24.464) between (-5.5, 24.464) and (-10.5, 24.464); A3 r 2 centre (-8, 24.464) between (-6, 24.464) and (-10, 24.464); 1 further point
  constraints: 4 end point, 4 point on circle, 2 centre point, 2 coincident, 1 collinear, 1 parallel
  dimensions: "d3845" = 0.5 distance of L3.start L3.end
extrude "押し出し219" join sketch "スケッチ230" distance "d3846" = 0.5; taper "d3847" = 0 deg
sketch "スケッチ231"
  geometry: L1 (113.588, -38.314)-(103.588, -38.314) reference; L2 (113.588, -18.314)-(113.588, -38.314) reference; L3 (12.588, -8.314)-(12.588, -19.314) reference; L4 (13.588, -22.314)-(56.588, -22.314) reference; C1 r 1 at (83.588, -33.314); C2 r 1 at (95.588, -33.314); C3 r 1 at (107.588, -33.314); C4 r 1 at (17.588, -17.314); 1 further point
  constraints: 4 centre point
  dimensions: "d3848" = 2 diameter of C2; "d3850" = 12 distance of C1.centre C2.centre; "d3851" = 5 distance from line of L3 C4.centre; "d3852" = 5 distance from line of L4 C4.centre; "d3853" = 5 distance from line of L1 C3.centre; "d3854" = 12 distance of C3.centre C2.centre; "d3855" = 0 vertical distance of C2.centre C3.centre; "d3856" = 0 vertical distance of C1.centre C2.centre; "d3864" = 2 diameter of C1; "d3865" = 6 distance from line of L2 C3.centre; "d3866" = 2 diameter of C3; "d3867" = 2 diameter of C4
extrude "talltrees" join sketch "スケッチ231" distance "d3868" = 16; taper "d3869" = 0 deg
sketch "スケッチ232" dims "d1265" = 0
  geometry: L1 (-0.4, 3)-(0.4, 3); L2 (0.4, 3)-(0.4, -3); L3 (0.4, -3)-(-0.4, -3); L4 (-0.4, -3)-(-0.4, 3); L5 (-12.4, 3)-(-11.6, 3); L6 (-11.6, 3)-(-11.6, -3); L7 (-11.6, -3)-(-12.4, -3); L8 (-12.4, -3)-(-12.4, 3); L9 (-24.4, 3)-(-23.6, 3); L10 (-23.6, 3)-(-23.6, -3); L11 (-23.6, -3)-(-24.4, -3); L12 (-24.4, -3)-(-24.4, 3); L13 (-27, 0.4)-(-21, 0.4); L14 (-21, 0.4)-(-21, -0.4); L15 (-21, -0.4)-(-27, -0.4); L16 (-27, -0.4)-(-27, 0.4); L17 (-15, 0.4)-(-9, 0.4); L18 (-9, 0.4)-(-9, -0.4); L19 (-9, -0.4)-(-15, -0.4); L20 (-15, -0.4)-(-15, 0.4); L21 (-3, 0.4)-(3, 0.4); L22 (3, 0.4)-(3, -0.4); L23 (3, -0.4)-(-3, -0.4); L24 (-3, -0.4)-(-3, 0.4); L25 (-90.4, 19)-(-89.6, 19); L26 (-89.6, 19)-(-89.6, 13); L27 (-89.6, 13)-(-90.4, 13); L28 (-90.4, 13)-(-90.4, 19); L29 (-93, 16.4)-(-87, 16.4); L30 (-87, 16.4)-(-87, 15.6); L31 (-87, 15.6)-(-93, 15.6); L32 (-93, 15.6)-(-93, 16.4); C1 r 1 at (0, 0) reference; 1 further point
  constraints: 64 end point, 16 parallel, 8 horizontal, 8 perpendicular
  dimensions: "d3870" = 0.8 distance of L21.end L22.end; "d3872" = 0.8 distance of L1.start L1.end; "d3873" = 0.8 distance of L5.start L5.end; "d3874" = 0.8 distance of L9.start L9.end; "d3875" = 0.4 distance from line of L2 C1.centre; "d3876" = 12 distance between parallel lines of L8 L4; "d3877" = 12 distance between parallel lines of L12 L8; "d3878" = 6 distance of L1.end L2.end; "d3879" = 3 distance from line of C1.centre L1; "d3880" = 6 distance of L21.start L21.end; "d3881" = 6 distance of L17.start L17.end; "d3882" = 6 distance of L13.start L13.end; "d3883" = 0 distance between parallel lines of L3 L7; "d3884" = 0 distance between parallel lines of L11 L7; "d3885" = 0.4 distance from line of L21 C1.centre; "d3886" = 0 distance between parallel lines of L17 L21; "d3887" = 0 distance between parallel lines of L13 L17; "d3888" = 12 distance from line of L22.end L18; "d3889" = 12 distance between parallel lines of L14 L18; "d3890" = 3 distance from line of L22 C1.centre; "d3891" = 6 distance of L29.start L29.end; "d3892" = 6 distance of L25.end L26.end; "d3893" = 0.8 distance of L25.start L25.end; "d3894" = 0.8 distance of L29.end L30.end; "d3895" = 2.6 distance between parallel lines of L30 L26; "d3896" = 2.6 distance between parallel lines of L29 L25; "d3897" = 65.2 distance between parallel lines of L12 L26; "d3898" = 16 distance between parallel lines of L15 L31; "d3899" = 0 distance between parallel lines of L15 L19; "d3900" = 0 distance between parallel lines of L23 L19; "d3919" = 0 distance between parallel lines of L5 L9; "d3920" = 0 distance between parallel lines of L1 L5
extrude "押し出し221" join sketch "スケッチ232" distance "d3901" = 20; taper "d3902" = 0 deg
sketch "スケッチ233"
  geometry: L1 (0.4, -3)-(0.4, -0.4) reference; L2 (0.4, -0.4)-(3, -0.4) reference; L3 (-0.4, 3)-(-0.4, 0.4) reference; L4 (-0.4, 0.4)-(-3, 0.4) reference; L5 (-0.4, 1.7)-(0.4, 1.7); L6 (0.4, 1.7)-(0.4, -1.7); L7 (0.4, -1.7)-(-0.4, -1.7); L8 (-0.4, -1.7)-(-0.4, 1.7); L9 (-1.7, 0.4)-(1.7, 0.4); L10 (1.7, 0.4)-(1.7, -0.4); L11 (1.7, -0.4)-(-1.7, -0.4); L12 (-1.7, -0.4)-(-1.7, 0.4); L13 (-12.367, 2)-(-11.641, 2); L14 (-11.641, 2)-(-11.641, -1.7); L15 (-11.641, -1.7)-(-12.367, -1.7); L16 (-12.367, -1.7)-(-12.367, 2); L17 (-14, 0.4)-(-10, 0.4); L18 (-10, 0.4)-(-10, -0.4); L19 (-10, -0.4)-(-14, -0.4); L20 (-14, -0.4)-(-14, 0.4); L21 (-24.4, 2)-(-23.6, 2); L22 (-23.6, 2)-(-23.6, -2); L23 (-23.6, -2)-(-24.4, -2); L24 (-24.4, -2)-(-24.4, 2); L25 (-26.075, 0.4)-(-22.075, 0.4); L26 (-22.075, 0.4)-(-22.075, -0.4); L27 (-22.075, -0.4)-(-26.075, -0.4); L28 (-26.075, -0.4)-(-26.075, 0.4); L29 (-90.4, 18)-(-89.6, 18); L30 (-89.6, 18)-(-89.6, 14); L31 (-89.6, 14)-(-90.4, 14); L32 (-90.4, 14)-(-90.4, 18); L33 (-92, 16.4)-(-88, 16.4); L34 (-88, 16.4)-(-88, 15.6); L35 (-88, 15.6)-(-92, 15.6); L36 (-92, 15.6)-(-92, 16.4); L37 (-24.4, -3)-(-23.6, -3) reference; L38 (-24.4, -0.4)-(-24.4, -3) reference; L39 (-90.4, 19)-(-90.4, 16.4) reference; L40 (-87, 16.4)-(-89.6, 16.4) reference; L41 (-87, 15.6)-(-87, 16.4) reference; L42 (-90.4, 13)-(-89.6, 13) reference; L43 (-9, -0.4)-(-9, 0.4) reference; 1 further point
  constraints: 64 end point, 16 parallel, 8 horizontal, 8 perpendicular, 4 midpoint
  dimensions: "d3903" = 4 distance of L25.start L25.end; "d3905" = 4 distance of L21.end L22.end; "d3906" = 1 distance between parallel lines of L37 L23; "d3907" = 0 distance between parallel lines of L38 L24; "d3908" = 0.8 distance of L22.end L23.end; "d3909" = 0.8 distance of L30.end L31.end; "d3910" = 0.8 distance of L33.end L34.end; "d3911" = 0 distance between parallel lines of L39 L32; "d3912" = 0 distance between parallel lines of L40 L33; "d3913" = 4 distance of L33.start L33.end; "d3914" = 1 distance between parallel lines of L41 L34; "d3915" = 4 distance of L29.end L30.end; "d3916" = 1 distance between parallel lines of L42 L31; "d3937" = 0 distance between parallel lines of L13 L21; "d3941" = 4 distance of L17.start L17.end; "d3942" = 1 distance between parallel lines of L43 L18
extrude "押し出し222" join sketch "スケッチ233" distance "d3917" = 12; taper "d3918" = 0 deg
sketch "スケッチ234"
  geometry: C1 r 0.6 at (-0.024, 0.024); C2 r 0.6 at (-24.024, 0.024); 1 further point
  constraints: 2 centre point
  dimensions: "d3921" = 24 distance of C1.centre C2.centre; "d3923" = 1.2 diameter of C1; "d3924" = 1.2 diameter of C2
extrude "押し出し223" join sketch "スケッチ234" distance "d3925" = 12; taper "d3926" = 0 deg
sketch "スケッチ235"
  geometry: L1 (-10, 0.4)-(-11.641, 0.4) reference; L2 (-12.367, -0.4)-(-12.367, -1.7) reference; C1 r 0.6 at (-11.967, 0); C2 r 0.6 at (-90.024, 16.054); 1 further point
  constraints: 2 centre point
  dimensions: "d3927" = 1.2 diameter of C2; "d3929" = 1.2 diameter of C1; "d3930" = 0.4 distance from line of L2 C1.centre; "d3931" = 0.4 distance from line of L1 C1.centre
extrude "押し出し224" join sketch "スケッチ235" distance "d3932" = 6; taper "d3933" = 0 deg
chamfer "面取り2" distance "d3934" = 2; stored, may be unused: second distance "d3935" = 2, angle "d3936" = 45 deg
chamfer "面取り3" distance "d3938" = 0.8; stored, may be unused: second distance "d3939" = 2, angle "d3940" = 45 deg
sketch "スケッチ236"
  geometry: L1 (113.588, -38.314)-(103.588, -38.314) reference; L2 (113.588, -18.314)-(113.588, -38.314) reference; L3 (58.238, 31.686)-(58.238, 13.103) reference; L4 (58.238, 13.103)-(26.588, 13.103) reference; C1 r 0.8 at (107.588, -23.314); C2 r 0.8 at (95.588, -23.314); C3 r 0.8 at (44.238, 21.103); C4 r 0.8 at (30.238, 21.103); 1 further point
  constraints: 4 centre point
  dimensions: "d3943" = 14 distance of C3.centre C4.centre; "d3944" = 12 distance of C1.centre C2.centre; "d3945" = 6 distance from line of L2 C1.centre; "d3946" = 15 distance from line of L1 C1.centre; "d3947" = 14 distance from line of L3 C3.centre; "d3948" = 8 distance from line of L4 C3.centre; "d3949" = 1.6 diameter of C1; "d3950" = 1.6 diameter of C2; "d3951" = 1.6 diameter of C3; "d3952" = 1.6 diameter of C4
extrude "押し出し225" join sketch "スケッチ236" distance "d3953" = 8; taper "d3954" = 0 deg
sketch "スケッチ237"
  geometry: L1 (-3, 0.4)-(3, 0.4); L2 (3, 0.4)-(3, -0.4); L3 (3, -0.4)-(-3, -0.4); L4 (-3, -0.4)-(-3, 0.4); L5 (-0.4, 3)-(0.4, 3); L6 (0.4, 3)-(0.4, -3); L7 (0.4, -3)-(-0.4, -3); L8 (-0.4, -3)-(-0.4, 3); L9 (-15, 0.4)-(-9, 0.4); L10 (-9, 0.4)-(-9, -0.4); L11 (-9, -0.4)-(-15, -0.4); L12 (-15, -0.4)-(-15, 0.4); L13 (-12.4, 3)-(-11.6, 3); L14 (-11.6, 3)-(-11.6, -3); L15 (-11.6, -3)-(-12.4, -3); L16 (-12.4, -3)-(-12.4, 3); L17 (5, 35)-(5, 5) reference; L18 (5, 5)-(6, 5) reference; L19 (-80.35, 44.8)-(-74.35, 44.8); L20 (-74.35, 44.8)-(-74.35, 44); L21 (-74.35, 44)-(-80.35, 44); L22 (-80.35, 44)-(-80.35, 44.8); L23 (-66.35, 44.8)-(-60.35, 44.8); L24 (-60.35, 44.8)-(-60.35, 44); L25 (-60.35, 44)-(-66.35, 44); L26 (-66.35, 44)-(-66.35, 44.8); L27 (-77.759, 47.25)-(-76.959, 47.25); L28 (-76.959, 47.25)-(-76.959, 41.25); L29 (-76.959, 41.25)-(-77.759, 41.25); L30 (-77.759, 41.25)-(-77.759, 47.25); L31 (-63.75, 47.25)-(-62.95, 47.25); L32 (-62.95, 47.25)-(-62.95, 41.25); L33 (-62.95, 41.25)-(-63.75, 41.25); L34 (-63.75, 41.25)-(-63.75, 47.25); L35 (-82.434, 55)-(-48, 55) reference; L36 (-49.35, 36.417)-(-49.35, 55) reference; 1 further point
  constraints: 64 end point, 16 parallel, 8 horizontal, 8 perpendicular, 1 point on line
  dimensions: "d3955" = 0.8 distance of L1.end L2.end; "d3957" = 6 distance between parallel lines of L10 L4; "d3958" = 6 distance of L1.start L1.end; "d3959" = 6 distance of L9.start L9.end; "d3960" = 2 distance between parallel lines of L2 L17; "d3961" = 4.6 distance between parallel lines of L1 L18; "d3962" = 0 distance between parallel lines of L9 L1; "d3963" = 2.6 distance between parallel lines of L12 L16; "d3964" = 0.8 distance of L13.start L13.end; "d3965" = 6 distance of L15.end L13.start; "d3966" = 2.6 distance between parallel lines of L9 L13; "d3967" = 2.6 distance between parallel lines of L4 L8; "d3968" = 0 distance between parallel lines of L15 L7; "d3969" = 0 distance between parallel lines of L13 L5; "d3970" = 0.8 distance of L27.start L27.end; "d3971" = 0.8 distance of L31.start L31.end; "d3972" = 0.8 distance of L23.end L24.end; "d3973" = 0.8 distance of L19.end L20.end; "d3974" = 6 distance of L19.start L19.end; "d3975" = 6 distance of L23.start L23.end; "d3976" = 6 distance of L31.end L32.end; "d3977" = 6 distance of L29.end L27.start; "d3978" = 7.75 distance between parallel lines of L31 L35; "d3979" = 11 distance between parallel lines of L36 L24; "d3980" = 0 distance between parallel lines of L31 L27; "d3981" = 13.6 distance between parallel lines of L36 L32; "d3982" = 10.2 distance between parallel lines of L35 L23; "d3983" = 0 distance between parallel lines of L19 L23; "d3984" = 8 distance between parallel lines of L26 L20; "d3987" = 0.8 distance of L5.start L5.end
extrude "押し出し226" join sketch "スケッチ237" distance "d3985" = 16; taper "d3986" = 0 deg
sketch "スケッチ238"
  geometry: L1 (-9.25, 20.536)-(-9.25, 28.036) reference; L2 (-9.25, 28.036)-(-5.25, 28.036) reference; L3 (-5.25, 28.036)-(-5.25, 20.536) reference; L4 (-5.25, 20.536)-(-9.25, 20.536) reference; L5 (0.5, 16.536)-(0.5, 32.4) reference; L6 (-9.75, 27.536)-(-9.75, 28.536); L7 (-9.75, 28.536)-(-4.75, 28.536); L8 (-4.75, 28.536)-(-4.75, 27.536); L9 (-4.75, 27.536)-(-5.25, 27.536); L10 (-5.25, 27.536)-(-5.25, 28.036); L11 (-5.25, 28.036)-(-9.25, 28.036); L12 (-9.25, 28.036)-(-9.25, 27.536); L13 (-9.25, 27.536)-(-9.75, 27.536); L14 (-9.75, 23.036)-(-4.75, 23.036); L15 (-4.75, 23.036)-(-4.75, 20.036); L16 (-4.75, 20.036)-(-9.75, 20.036); L17 (-9.75, 20.036)-(-9.75, 23.036); L18 (30.75, 23.036)-(35.75, 23.036); L19 (35.75, 23.036)-(35.75, 20.036); L20 (35.75, 20.036)-(30.75, 20.036); L21 (30.75, 20.036)-(30.75, 23.036); L22 (30.75, 5.5)-(35.75, 5.5); L23 (35.75, 5.5)-(35.75, 2.5); L24 (35.75, 2.5)-(30.75, 2.5); L25 (30.75, 2.5)-(30.75, 5.5); L26 (-4.75, 5.5)-(-9.75, 5.5); L27 (-9.75, 5.5)-(-9.75, 2.5); L28 (-9.75, 2.5)-(-4.75, 2.5); L29 (-4.75, 2.5)-(-4.75, 5.5); L30 (30.75, 27.536)-(30.75, 28.536); L31 (30.75, 28.536)-(35.75, 28.536); L32 (35.75, 28.536)-(35.75, 27.536); L33 (35.75, 27.536)-(35.25, 27.536); L34 (35.25, 27.536)-(35.25, 28.036); L35 (35.25, 28.036)-(31.25, 28.036); L36 (31.25, 28.036)-(31.25, 27.536); L37 (31.25, 27.536)-(30.75, 27.536); L38 (31.25, 20.536)-(31.25, 27.981) reference; L39 (35.25, 27.981)-(35.25, 20.536) reference; L40 (35.25, 3)-(31.25, 3) reference; L41 (31.251, 10.455)-(30.751, 10.455); L42 (35.25, 10.5)-(35.75, 10.5); L43 (-9.75, 10.5)-(-9.242, 10.5); L44 (-5.258, 10.5)-(-4.75, 10.5); A1 r 2.5 centre (33.25, 10.5) between (35.75, 10.5) and (30.751, 10.455); A2 r 2 centre (33.25, 10.5) between (35.25, 10.5) and (31.251, 10.455); A3 r 2.5 centre (-7.25, 10.5) between (-4.75, 10.5) and (-9.75, 10.5); A4 r 1.992 centre (-7.25, 10.5) between (-5.258, 10.5) and (-9.242, 10.5); 1 further point
  constraints: 72 end point, 19 parallel, 9 perpendicular, 8 point on circle, 4 centre point, 4 horizontal, 3 collinear, 2 coincident, 2 point on line
  dimensions: "d3996" = 0.5 distance of L12.end L6.start; "d3998" = 0.5 distance of L8.end L9.end; "d3999" = 1 distance of L7.end L8.end; "d4000" = 0.5 distance between parallel lines of L2 L7; "d4001" = 0 distance between parallel lines of L13 L9; "d4002" = 0.5 distance between parallel lines of L16 L4; "d4003" = 0.5 distance of L36.end L30.start; "d4004" = 0.5 distance of L32.end L33.end; "d4005" = 0 distance between parallel lines of L31 L7; "d4006" = 0 distance between parallel lines of L35 L2; "d4007" = 1 distance of L31.end L32.end; "d4008" = 0 distance between parallel lines of L37 L33; "d4009" = 0 distance between parallel lines of L36 L38; "d4010" = 0 distance between parallel lines of L39 L34; "d4011" = 3 distance of L14.end L15.end; "d4012" = 0 distance between parallel lines of L15 L8; "d4013" = 0 distance between parallel lines of L17 L6; "d4014" = 0 distance between parallel lines of L16 L20; "d4015" = 0 distance between parallel lines of L18 L14; "d4016" = 0 distance between parallel lines of L19 L32; "d4017" = 0 distance between parallel lines of L21 L30; "d4018" = 0 distance between parallel lines of L23 L19; "d4019" = 0 distance between parallel lines of L25 L21; "d4020" = 3 distance of L22.end L23.end; "d4021" = 0.5 distance between parallel lines of L40 L24; "d4022" = 0 distance between parallel lines of L24 L28; "d4023" = 0 distance between parallel lines of L22 L26; "d4024" = 0 distance between parallel lines of L29 L15; "d4025" = 0 distance between parallel lines of L17 L27; "d4026" = 0 vertical distance of L42.start A2.centre; "d4027" = 5 distance from line of L22 A1.centre; "d4028" = 0 vertical distance of L43.end A4.centre; "d4029" = 5 distance from line of L26 A3.centre; "d4030" = 0 distance from line of L44 A3.centre; "d4031" = 0 distance from line of L29 L44.end
extrude "押し出し227" join sketch "スケッチ238" distance "d4032" = 0.5; taper "d4033" = 0 deg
